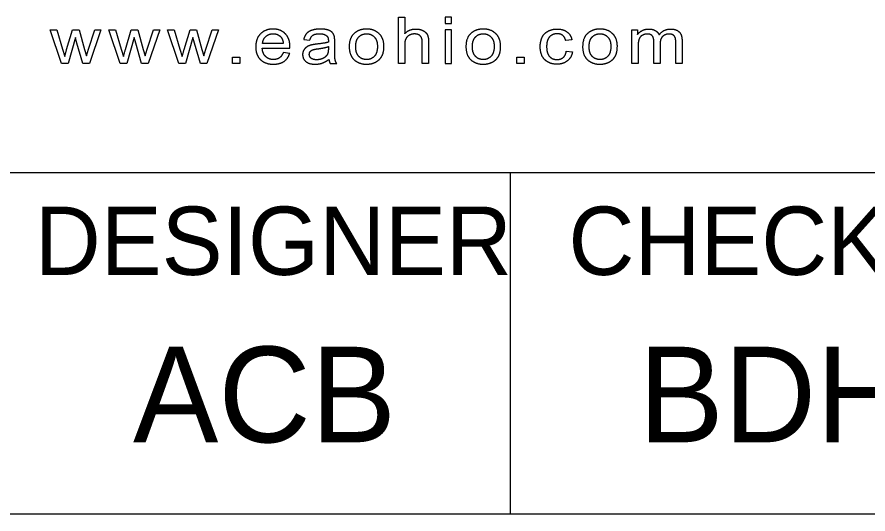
# Model space of a CAD drawing. Extents: x 0 to 34, y -10.4 to 22.
# Drawn here: x 32.028 to 33.274, y 2.5 to 3.228 of the extents above; entities that cross this region are included whole.
import ezdxf

# ---------------------------------------------------------------- set-up
doc = ezdxf.new("R2010")
doc.units = 0
for name, color, linetype in [('SH_Border', 7, 'Continuous'), ('SH_Data', 7, 'Continuous'), ('TX_X_20', 7, 'Continuous')]:
    doc.layers.add(name, color=color, linetype=linetype)

msp = doc.modelspace()

# ---------------------------------------------------------------- linework, layer by layer
at = {"layer": 'SH_Border'}
for p, q in [((32, 3), (33.5, 3)), ((32.75, 3), (32.75, 2.5)), ((32, 2.5), (33.5, 2.5))]:
    msp.add_line(p, q, dxfattribs=at)
at = {"layer": 'TX_X_20'}
for p, q in [((32.4178, 3.1889), (32.3875, 3.1889)), ((32.4477, 3.1948), (32.4567, 3.1937)), ((32.4931, 3.1802), (32.4931, 3.1913)), ((32.8402, 3.1944), (32.8313, 3.1931)), ((32.387, 3.1821), (32.4274, 3.1821)), ((32.4838, 3.1843), (32.4838, 3.1812)), ((32.5143, 3.1842), (32.5143, 3.1842)), ((32.5238, 3.1842), (32.5238, 3.1842)), ((32.6852, 3.1842), (32.6852, 3.1842)), ((32.6946, 3.1842), (32.6946, 3.1842)), ((32.8321, 3.1776), (32.8411, 3.1765)), ((32.856, 3.1842), (32.856, 3.1842)), ((32.8655, 3.1842), (32.8655, 3.1842)), ((32.4272, 3.1744), (32.4177, 3.1755)), ((32.4846, 3.1656), (32.4846, 3.1656)), ((32.4864, 3.1596), (32.496, 3.1596))]:
    msp.add_line(p, q, dxfattribs=at)
for points in [[(32.5955, 3.1865), (32.5955, 3.1596), (32.5863, 3.1596), (32.5863, 3.2276), (32.5955, 3.2276), (32.5955, 3.2032)], [(32.1007, 3.18), (32.1093, 3.2089), (32.1188, 3.2089), (32.1269, 3.1802), (32.1295, 3.1708), (32.1327, 3.1804), (32.142, 3.2089), (32.1509, 3.2089), (32.1339, 3.1596), (32.1244, 3.1596), (32.1158, 3.1891), (32.1137, 3.1975), (32.1027, 3.1596), (32.0931, 3.1596), (32.0766, 3.2089), (32.0861, 3.2089), (32.0947, 3.1804), (32.0979, 3.1698)], [(32.1867, 3.18), (32.1953, 3.2089), (32.2048, 3.2089), (32.2129, 3.1802), (32.2155, 3.1708), (32.2186, 3.1804), (32.228, 3.2089), (32.2369, 3.2089), (32.2199, 3.1596), (32.2104, 3.1596), (32.2018, 3.1891), (32.1997, 3.1975), (32.1886, 3.1596), (32.179, 3.1596), (32.1625, 3.2089), (32.172, 3.2089), (32.1807, 3.1804), (32.1838, 3.1698)], [(32.2726, 3.18), (32.2813, 3.2089), (32.2907, 3.2089), (32.2988, 3.1802), (32.3015, 3.1708), (32.3046, 3.1804), (32.3139, 3.2089), (32.3229, 3.2089), (32.3059, 3.1596), (32.2964, 3.1596), (32.2878, 3.1891), (32.2856, 3.1975), (32.2746, 3.1596), (32.265, 3.1596), (32.2485, 3.2089), (32.258, 3.2089), (32.2666, 3.1804), (32.2698, 3.1698)], [(32.9372, 3.1851), (32.9372, 3.1596), (32.928, 3.1596), (32.928, 3.2089), (32.9362, 3.2089), (32.9362, 3.2019)], [(32.6305, 3.1908), (32.6305, 3.1596), (32.6213, 3.1596), (32.6213, 3.1908)], [(32.9694, 3.1882), (32.9694, 3.1596), (32.9602, 3.1596), (32.9602, 3.1916)], [(33.0015, 3.1934), (33.0015, 3.1596), (32.9923, 3.1596), (32.9923, 3.1906)]]:
    msp.add_lwpolyline(points, dxfattribs=at)
for points in [[(32.655, 3.218), (32.6642, 3.218), (32.6642, 3.2276), (32.655, 3.2276)], [(32.655, 3.1596), (32.6642, 3.1596), (32.6642, 3.2089), (32.655, 3.2089)], [(32.3437, 3.1596), (32.3437, 3.169), (32.3541, 3.169), (32.3541, 3.1596)], [(32.7597, 3.1596), (32.7597, 3.169), (32.7702, 3.169), (32.7702, 3.1596)]]:
    msp.add_lwpolyline(points, close=True, dxfattribs=at)
for points in [[(32.3846, 3.2031), (32.3775, 3.1962), (32.3775, 3.1838)], [(32.4028, 3.21), (32.3916, 3.21), (32.3846, 3.2031)], [(32.3923, 3.1992), (32.3966, 3.2031), (32.4029, 3.2031)], [(32.4206, 3.2032), (32.4137, 3.21), (32.4028, 3.21)], [(32.4029, 3.2031), (32.4099, 3.2031), (32.4143, 3.1983)], [(32.4275, 3.1843), (32.4275, 3.1965), (32.4206, 3.2032)], [(32.4517, 3.2032), (32.4489, 3.2), (32.4477, 3.1948)], [(32.4598, 3.2082), (32.4545, 3.2065), (32.4517, 3.2032)], [(32.4721, 3.21), (32.4651, 3.21), (32.4598, 3.2082)], [(32.4612, 3.201), (32.4643, 3.2031), (32.4708, 3.2031)], [(32.4708, 3.2031), (32.4777, 3.2031), (32.4812, 3.2002)], [(32.4834, 3.2085), (32.479, 3.21), (32.4721, 3.21)], [(32.4897, 3.2047), (32.4877, 3.207), (32.4834, 3.2085)], [(32.4926, 3.199), (32.4918, 3.2025), (32.4897, 3.2047)], [(32.5227, 3.2045), (32.5143, 3.1979), (32.5143, 3.1842)], [(32.5398, 3.21), (32.5297, 3.21), (32.5227, 3.2045)], [(32.5283, 3.1984), (32.5329, 3.2031), (32.5398, 3.2031)], [(32.558, 3.2033), (32.5509, 3.21), (32.5398, 3.21)], [(32.5398, 3.2031), (32.5465, 3.2031), (32.5511, 3.1983)], [(32.5651, 3.1849), (32.5651, 3.1966), (32.558, 3.2033)], [(32.5955, 3.2032), (32.602, 3.21), (32.6118, 3.21)], [(32.6099, 3.2028), (32.6058, 3.2028), (32.6022, 3.2008)], [(32.6183, 3.1999), (32.6153, 3.2028), (32.6099, 3.2028)], [(32.6118, 3.21), (32.6178, 3.21), (32.6222, 3.2078)], [(32.6222, 3.2078), (32.6267, 3.2056), (32.6286, 3.2018)], [(32.6286, 3.2018), (32.6305, 3.198), (32.6305, 3.1908)], [(32.6935, 3.2045), (32.6852, 3.1979), (32.6852, 3.1842)], [(32.7106, 3.21), (32.7005, 3.21), (32.6935, 3.2045)], [(32.6992, 3.1984), (32.7037, 3.2031), (32.7106, 3.2031)], [(32.7288, 3.2033), (32.7218, 3.21), (32.7106, 3.21)], [(32.7106, 3.2031), (32.7174, 3.2031), (32.7219, 3.1983)], [(32.7359, 3.1849), (32.7359, 3.1966), (32.7288, 3.2033)], [(32.7968, 3.198), (32.7997, 3.204), (32.8056, 3.207)], [(32.8056, 3.207), (32.8116, 3.21), (32.8186, 3.21)], [(32.8189, 3.2031), (32.812, 3.2031), (32.8077, 3.1986)], [(32.8186, 3.21), (32.8274, 3.21), (32.833, 3.2059)], [(32.8268, 3.2006), (32.8235, 3.2031), (32.8189, 3.2031)], [(32.833, 3.2059), (32.8387, 3.2018), (32.8402, 3.1944)], [(32.8644, 3.2045), (32.856, 3.1979), (32.856, 3.1842)], [(32.8814, 3.21), (32.8714, 3.21), (32.8644, 3.2045)], [(32.87, 3.1984), (32.8745, 3.2031), (32.8814, 3.2031)], [(32.8997, 3.2033), (32.8926, 3.21), (32.8814, 3.21)], [(32.8814, 3.2031), (32.8882, 3.2031), (32.8927, 3.1983)], [(32.9068, 3.1849), (32.9068, 3.1966), (32.8997, 3.2033)], [(32.9362, 3.2019), (32.9388, 3.2055), (32.943, 3.2077)], [(32.943, 3.2077), (32.9472, 3.21), (32.9527, 3.21)], [(32.9506, 3.2027), (32.9467, 3.2027), (32.9434, 3.2008)], [(32.958, 3.1999), (32.9557, 3.2027), (32.9506, 3.2027)], [(32.9527, 3.21), (32.9587, 3.21), (32.9625, 3.2077)], [(32.9625, 3.2077), (32.9664, 3.2054), (32.968, 3.2013)], [(32.968, 3.2013), (32.9744, 3.21), (32.9847, 3.21)], [(32.9827, 3.2027), (32.977, 3.2027), (32.9732, 3.1992)], [(32.9882, 3.2014), (32.9858, 3.2027), (32.9827, 3.2027)], [(32.9847, 3.21), (32.9928, 3.21), (32.9972, 3.2059)], [(32.9914, 3.1978), (32.9905, 3.2), (32.9882, 3.2014)], [(32.9972, 3.2059), (33.0015, 3.2018), (33.0015, 3.1934)], [(32.3875, 3.1889), (32.388, 3.1954), (32.3923, 3.1992)], [(32.4143, 3.1983), (32.4172, 3.1951), (32.4178, 3.1889)], [(32.4567, 3.1937), (32.4581, 3.1989), (32.4612, 3.201)], [(32.4838, 3.1908), (32.4785, 3.1892), (32.4674, 3.188)], [(32.4812, 3.2002), (32.4838, 3.1981), (32.4838, 3.193)], [(32.4838, 3.193), (32.4838, 3.1925), (32.4838, 3.1908)], [(32.4931, 3.1913), (32.4931, 3.1969), (32.4926, 3.199)], [(32.5238, 3.1842), (32.5238, 3.1937), (32.5283, 3.1984)], [(32.5511, 3.1983), (32.5556, 3.1936), (32.5556, 3.1845)], [(32.5971, 3.1956), (32.5955, 3.1923), (32.5955, 3.1865)], [(32.6022, 3.2008), (32.5986, 3.1989), (32.5971, 3.1956)], [(32.6213, 3.1908), (32.6213, 3.197), (32.6183, 3.1999)], [(32.6946, 3.1842), (32.6946, 3.1937), (32.6992, 3.1984)], [(32.7219, 3.1983), (32.7265, 3.1936), (32.7265, 3.1845)], [(32.7939, 3.184), (32.7939, 3.192), (32.7968, 3.198)], [(32.8077, 3.1986), (32.8033, 3.1941), (32.8033, 3.1843)], [(32.8313, 3.1931), (32.83, 3.1981), (32.8268, 3.2006)], [(32.8655, 3.1842), (32.8655, 3.1937), (32.87, 3.1984)], [(32.8927, 3.1983), (32.8973, 3.1936), (32.8973, 3.1845)], [(32.9387, 3.1954), (32.9372, 3.1918), (32.9372, 3.1851)], [(32.9434, 3.2008), (32.9401, 3.199), (32.9387, 3.1954)], [(32.9602, 3.1916), (32.9602, 3.1971), (32.958, 3.1999)], [(32.9732, 3.1992), (32.9694, 3.1958), (32.9694, 3.1882)], [(32.9923, 3.1906), (32.9923, 3.1956), (32.9914, 3.1978)], [(32.0979, 3.1698), (32.0981, 3.1706), (32.1007, 3.18)], [(32.1838, 3.1698), (32.184, 3.1706), (32.1867, 3.18)], [(32.2698, 3.1698), (32.27, 3.1706), (32.2726, 3.18)], [(32.3775, 3.1838), (32.3775, 3.1718), (32.3845, 3.1651)], [(32.3921, 3.1696), (32.3875, 3.1739), (32.387, 3.1821)], [(32.4274, 3.1821), (32.4275, 3.1835), (32.4275, 3.1843)], [(32.4479, 3.1792), (32.4461, 3.1762), (32.4461, 3.1726)], [(32.4526, 3.184), (32.4497, 3.1822), (32.4479, 3.1792)], [(32.4592, 3.1867), (32.4555, 3.1858), (32.4526, 3.184)], [(32.4559, 3.1728), (32.4559, 3.175), (32.4571, 3.1768)], [(32.4571, 3.1768), (32.4584, 3.1785), (32.4608, 3.1795)], [(32.4674, 3.188), (32.4619, 3.1873), (32.4592, 3.1867)], [(32.4608, 3.1795), (32.4631, 3.1804), (32.4688, 3.1811)], [(32.4688, 3.1811), (32.4788, 3.1824), (32.4838, 3.1843)], [(32.4838, 3.1812), (32.4838, 3.1757), (32.4823, 3.1729)], [(32.4936, 3.1655), (32.4931, 3.1686), (32.4931, 3.1802)], [(32.5143, 3.1842), (32.5143, 3.1717), (32.5214, 3.1651)], [(32.5283, 3.17), (32.5238, 3.1747), (32.5238, 3.1842)], [(32.5556, 3.1845), (32.5556, 3.1748), (32.5511, 3.1701)], [(32.562, 3.17), (32.5651, 3.1754), (32.5651, 3.1849)], [(32.6852, 3.1842), (32.6852, 3.1717), (32.6922, 3.1651)], [(32.6992, 3.17), (32.6946, 3.1747), (32.6946, 3.1842)], [(32.7265, 3.1845), (32.7265, 3.1748), (32.7219, 3.1701)], [(32.7328, 3.17), (32.7359, 3.1754), (32.7359, 3.1849)], [(32.8006, 3.1651), (32.7939, 3.1717), (32.7939, 3.184)], [(32.8033, 3.1843), (32.8033, 3.1743), (32.8075, 3.1698)], [(32.8275, 3.1683), (32.8311, 3.1713), (32.8321, 3.1776)], [(32.8411, 3.1765), (32.8396, 3.168), (32.8335, 3.1633)], [(32.856, 3.1842), (32.856, 3.1717), (32.863, 3.1651)], [(32.87, 3.17), (32.8655, 3.1747), (32.8655, 3.1842)], [(32.8973, 3.1845), (32.8973, 3.1748), (32.8928, 3.1701)], [(32.9036, 3.17), (32.9068, 3.1754), (32.9068, 3.1849)], [(32.3845, 3.1651), (32.3915, 3.1585), (32.4034, 3.1585)], [(32.4034, 3.1653), (32.3966, 3.1653), (32.3921, 3.1696)], [(32.412, 3.1677), (32.4085, 3.1653), (32.4034, 3.1653)], [(32.4177, 3.1755), (32.4156, 3.1702), (32.412, 3.1677)], [(32.4189, 3.1626), (32.4249, 3.1668), (32.4272, 3.1744)], [(32.4461, 3.1726), (32.4461, 3.1664), (32.4509, 3.1624)], [(32.4586, 3.1672), (32.4559, 3.1695), (32.4559, 3.1728)], [(32.4668, 3.165), (32.4614, 3.165), (32.4586, 3.1672)], [(32.4762, 3.1671), (32.4721, 3.165), (32.4668, 3.165)], [(32.4747, 3.1601), (32.4794, 3.1617), (32.4846, 3.1656)], [(32.4823, 3.1729), (32.4803, 3.1692), (32.4762, 3.1671)], [(32.4846, 3.1656), (32.485, 3.1622), (32.4864, 3.1596)], [(32.496, 3.1596), (32.4942, 3.1624), (32.4936, 3.1655)], [(32.5214, 3.1651), (32.5284, 3.1585), (32.5398, 3.1585)], [(32.5398, 3.1653), (32.5329, 3.1653), (32.5283, 3.17)], [(32.5511, 3.1701), (32.5466, 3.1653), (32.5398, 3.1653)], [(32.5528, 3.1615), (32.5588, 3.1645), (32.562, 3.17)], [(32.6922, 3.1651), (32.6992, 3.1585), (32.7106, 3.1585)], [(32.7106, 3.1653), (32.7037, 3.1653), (32.6992, 3.17)], [(32.7219, 3.1701), (32.7174, 3.1653), (32.7106, 3.1653)], [(32.7237, 3.1615), (32.7297, 3.1645), (32.7328, 3.17)], [(32.8185, 3.1585), (32.8074, 3.1585), (32.8006, 3.1651)], [(32.8075, 3.1698), (32.8117, 3.1653), (32.8185, 3.1653)], [(32.8185, 3.1653), (32.8239, 3.1653), (32.8275, 3.1683)], [(32.863, 3.1651), (32.87, 3.1585), (32.8814, 3.1585)], [(32.8814, 3.1653), (32.8745, 3.1653), (32.87, 3.17)], [(32.8928, 3.1701), (32.8882, 3.1653), (32.8814, 3.1653)], [(32.8945, 3.1615), (32.9005, 3.1645), (32.9036, 3.17)], [(32.4034, 3.1585), (32.4128, 3.1585), (32.4189, 3.1626)], [(32.4509, 3.1624), (32.4556, 3.1585), (32.4646, 3.1585)], [(32.4646, 3.1585), (32.47, 3.1585), (32.4747, 3.1601)], [(32.5398, 3.1585), (32.5468, 3.1585), (32.5528, 3.1615)], [(32.7106, 3.1585), (32.7177, 3.1585), (32.7237, 3.1615)], [(32.8335, 3.1633), (32.8274, 3.1585), (32.8185, 3.1585)], [(32.8814, 3.1585), (32.8885, 3.1585), (32.8945, 3.1615)]]:
    msp.add_open_spline(points, degree=2, dxfattribs=at)

# ---------------------------------------------------------------- texts
at = {"layer": 'SH_Data'}
for s, height, p in [('DESIGNER', 0.1, (32.054, 2.85)), ('CHECKER', 0.1, (32.8352, 2.85)), ('ACB', 0.14, (32.1979, 2.605)), ('BDH', 0.14, (32.9377, 2.605))]:
    msp.add_text(s, height=height, dxfattribs=at).set_placement(p)

doc.saveas('drawing.dxf')
